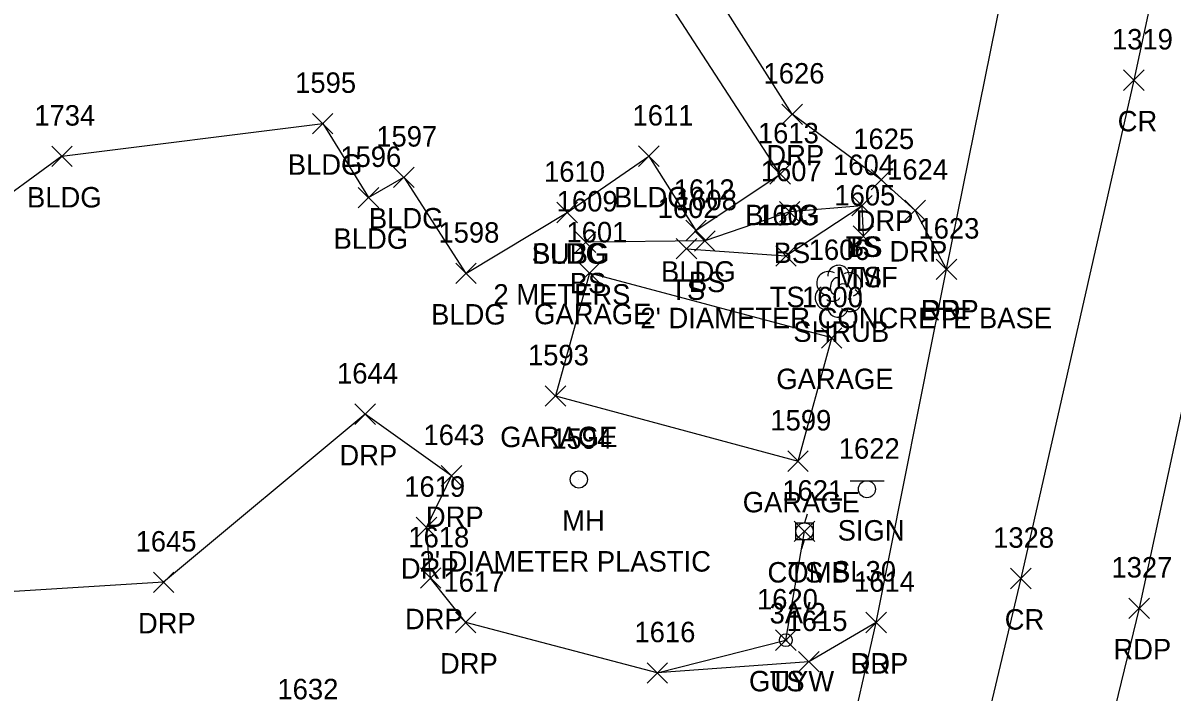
# Model space of a CAD drawing. Extents: x 1477930 to 1480780, y 774090 to 784647.
# Drawn here: x 1479284.7 to 1479397, y 774509.5 to 774574.9 of the extents above; entities that cross this region are included whole.
import ezdxf

# ---------------------------------------------------------------- set-up
doc = ezdxf.new("R2010")
doc.units = 0
for name, color, linetype in [('L_A', 7, 'Continuous'), ('L_C', 7, 'Continuous'), ('L_I', 7, 'Continuous'), ('L_TIC', 7, 'Continuous'), ('LBC', 7, 'Continuous'), ('LELB', 7, 'Continuous'), ('LSH', 7, 'Continuous'), ('P_A', 7, 'Continuous'), ('P_I', 7, 'Continuous'), ('P_TIC', 7, 'Continuous'), ('PET', 7, 'Continuous'), ('PRC', 7, 'Continuous'), ('R_A', 7, 'Continuous'), ('R_I', 7, 'Continuous'), ('R_TIC', 7, 'Continuous'), ('RDP', 7, 'Continuous'), ('S_A', 7, 'Continuous'), ('S_C', 7, 'Continuous'), ('S_I', 7, 'Continuous'), ('SSGN', 7, 'Continuous'), ('U_A', 7, 'Continuous'), ('U_C', 7, 'Continuous'), ('U_I', 7, 'Continuous'), ('U_TIC', 7, 'Continuous'), ('UP', 7, 'Continuous'), ('UPGW', 7, 'Continuous'), ('UUMH', 7, 'Continuous')]:
    doc.layers.add(name, color=color, linetype=linetype)

msp = doc.modelspace()

# ---------------------------------------------------------------- linework, layer by layer
at = {"layer": 'L_TIC'}
for points in [[(1479312.99, 774564.07), (1479314.99, 774566.07)], [(1479314.99, 774564.07), (1479312.99, 774566.07)], [(1479287.53, 774560.87), (1479289.53, 774562.87)], [(1479289.53, 774560.87), (1479287.53, 774562.87)], [(1479344.84, 774560.88), (1479346.84, 774562.88)], [(1479346.84, 774560.88), (1479344.84, 774562.88)], [(1479357.65, 774559.14), (1479359.65, 774561.14)], [(1479359.65, 774559.14), (1479357.65, 774561.14)], [(1479320.91, 774558.82), (1479322.91, 774560.82)], [(1479322.91, 774558.82), (1479320.91, 774560.82)], [(1479317.46, 774556.83), (1479319.46, 774558.83)], [(1479319.46, 774556.83), (1479317.46, 774558.83)], [(1479365.64, 774556.04), (1479367.64, 774558.04)], [(1479367.64, 774556.04), (1479365.64, 774558.04)], [(1479365.64, 774556.04), (1479367.64, 774558.04)], [(1479367.64, 774556.04), (1479365.64, 774558.04)], [(1479336.86, 774555.38), (1479338.86, 774557.38)], [(1479338.86, 774555.38), (1479336.86, 774557.38)], [(1479358.58, 774555.44), (1479360.58, 774557.44)], [(1479360.58, 774555.44), (1479358.58, 774557.44)], [(1479349.43, 774553.62), (1479351.43, 774555.62)], [(1479351.43, 774553.62), (1479349.43, 774555.62)], [(1479338.67, 774552.48), (1479340.67, 774554.48)], [(1479340.67, 774552.48), (1479338.67, 774554.48)], [(1479350.3, 774552.6), (1479352.3, 774554.6)], [(1479352.3, 774552.6), (1479350.3, 774554.6)], [(1479365.77, 774553.07), (1479367.77, 774555.07)], [(1479367.77, 774553.07), (1479365.77, 774555.07)], [(1479365.77, 774553.07), (1479367.77, 774555.07)], [(1479367.77, 774553.07), (1479365.77, 774555.07)], [(1479348.51, 774551.84), (1479350.51, 774553.84)], [(1479350.51, 774551.84), (1479348.51, 774553.84)], [(1479358.22, 774551.13), (1479360.22, 774553.13)], [(1479360.22, 774551.13), (1479358.22, 774553.13)], [(1479326.98, 774549.43), (1479328.98, 774551.43)], [(1479328.98, 774549.43), (1479326.98, 774551.43)], [(1479339.04, 774549.46), (1479341.04, 774551.46)], [(1479341.04, 774549.46), (1479339.04, 774551.46)], [(1479362.69, 774543.12), (1479364.69, 774545.12)], [(1479364.69, 774543.12), (1479362.69, 774545.12)], [(1479335.72, 774537.45), (1479337.72, 774539.45)], [(1479337.72, 774537.45), (1479335.72, 774539.45)], [(1479359.4, 774531.08), (1479361.4, 774533.08)], [(1479361.4, 774531.08), (1479359.4, 774533.08)], [(1479360.03, 774524.22), (1479362.03, 774526.22)], [(1479362.03, 774524.22), (1479360.03, 774526.22)], [(1479358.21, 774513.59), (1479360.21, 774515.59)], [(1479360.21, 774513.59), (1479358.21, 774515.59)], [(1479345.66, 774510.39), (1479347.66, 774512.39)], [(1479347.66, 774510.39), (1479345.66, 774512.39)]]:
    msp.add_lwpolyline(points, dxfattribs=at)
at = {"layer": 'LBC'}
for points in [[(1479288.53, 774561.87), (1479280.58, 774556.08), (1479280.86, 774553.15), (1479266.83, 774543.78), (1479264.18, 774547.87), (1479260.06, 774554.44), (1479272.44, 774562.55), (1479262.77, 774577.67), (1479295.55, 774599.42), (1479305.58, 774605.99), (1479303.57, 774609.45), (1479310.55, 774613.97), (1479312.86, 774610.52), (1479322.29, 774616.29), (1479331.34, 774602.22)], [(1479313.99, 774565.07), (1479318.46, 774557.83), (1479321.91, 774559.82), (1479327.98, 774550.43), (1479337.86, 774556.38), (1479345.84, 774561.88), (1479350.43, 774554.62), (1479358.65, 774560.14), (1479331.34, 774602.22)], [(1479288.53, 774561.87), (1479313.99, 774565.07)], [(1479336.72, 774538.45), (1479360.4, 774532.08), (1479363.69, 774544.12), (1479340.04, 774550.46)], [(1479340.04, 774550.46), (1479336.72, 774538.45)]]:
    msp.add_lwpolyline(points, dxfattribs=at)
at = {"layer": 'LELB'}
for points in [[(1479366.64, 774557.04), (1479359.58, 774556.44), (1479351.3, 774553.6), (1479339.67, 774553.48)], [(1479349.51, 774552.84), (1479359.22, 774552.13), (1479366.64, 774557.04), (1479366.77, 774554.07)], [(1479346.66, 774511.39), (1479359.21, 774514.59), (1479361.03, 774525.22)]]:
    msp.add_lwpolyline(points, dxfattribs=at)
at = {"layer": 'LSH'}
msp.add_line((1479364.31, 774548.74), (1479364.31, 774548.74), dxfattribs=at)
msp.add_line((1479364.31, 774548.74), (1479364.31, 774548.74), dxfattribs=at)
msp.add_arc((1479364.36, 774550.17), 1.05, 335.5272, 180.9563, dxfattribs=at)
for centre, major_axis, ratio, start_param, end_param in [((1479363.52, 774549.41), (1.21, -0.51), 0.895232, 1.570796, 4.712389), ((1479364.1, 774549.2), (-0.208, -0.792), 0.645439, 3.141593, 6.283185), ((1479365.35, 774549.32), (-1.14, -0.48), 0.949671, 1.570796, 4.712389), ((1479363.23, 774548.03), (0.58, -1.04), 0.959034, 3.141593, 6.283185), ((1479364.81, 774548.57), (-0.5, 0.667), 0.989748, 3.141593, 6.283185), ((1479365.31, 774547.91), (-1.09, 0.79), 0.841452, 1.570796, 4.712389), ((1479364.31, 774547.24), (0.26, 1.06), 0.942809, 1.570796, 4.712389), ((1479363.85, 774547.99), (-0.625, -0.083), 0.423636, 0, 3.141593)]:
    msp.add_ellipse(centre, major_axis=major_axis, ratio=ratio, start_param=start_param, end_param=end_param, dxfattribs=at)
at = {"layer": 'P_TIC'}
for points in [[(1479392.18, 774568.31), (1479394.18, 774570.31)], [(1479394.18, 774568.31), (1479392.18, 774570.31)], [(1479373.9, 774549.83), (1479375.9, 774551.83)], [(1479375.9, 774549.83), (1479373.9, 774551.83)], [(1479381.15, 774519.62), (1479383.15, 774521.62)], [(1479383.15, 774519.62), (1479381.15, 774521.62)], [(1479392.7, 774516.71), (1479394.7, 774518.71)], [(1479394.7, 774516.71), (1479392.7, 774518.71)], [(1479367.03, 774515.32), (1479369.03, 774517.32)], [(1479369.03, 774515.32), (1479367.03, 774517.32)]]:
    msp.add_lwpolyline(points, dxfattribs=at)
at = {"layer": 'PET'}
for points in [[(1479713.99, 774833.47), (1479663.95, 774806), (1479649, 774797.94), (1479602.12, 774772.9), (1479559.82, 774750.06), (1479518.06, 774728.17), (1479475.57, 774706.69), (1479465.7, 774701.25), (1479434.17, 774686.11), (1479428.66, 774666.26), (1479418.77, 774633.96), (1479413.82, 774614.69), (1479404.23, 774566.57), (1479393.7, 774517.71), (1479389.34, 774499.77)], [(1479290.45, 774211), (1479306.91, 774277.39), (1479311.78, 774295.77), (1479318.73, 774320.25), (1479320.95, 774328.78), (1479324.18, 774341.9), (1479331.38, 774365.72), (1479345.79, 774423.22), (1479362.09, 774490.12), (1479368.03, 774516.32), (1479374.9, 774550.83), (1479383.52, 774593.51), (1479391.98, 774640.39), (1479380.39, 774660.29), (1479367.57, 774658.29), (1479344.84, 774648.04), (1479309.03, 774631.85), (1479275.88, 774616.72), (1479247.66, 774604.4), (1479226.65, 774595.78), (1479182.4, 774576.78), (1479137.48, 774556.65)]]:
    msp.add_lwpolyline(points, dxfattribs=at)
at = {"layer": 'PRC'}
msp.add_lwpolyline([(1479418.32, 774694.97), (1479413.6, 774667.54), (1479403.41, 774616.88), (1479393.18, 774569.31), (1479382.15, 774520.62), (1479370.95, 774473.44), (1479362, 774437.8), (1479350.26, 774392.93), (1479347.88, 774382.5), (1479334.29, 774330.6), (1479333.84, 774328.63), (1479325.02, 774295.54), (1479313.51, 774250.57), (1479296.99, 774187.82), (1479284.93, 774140.68)], dxfattribs=at)
at = {"layer": 'R_TIC'}
for points in [[(1479358.82, 774564.98), (1479360.82, 774566.98)], [(1479360.82, 774564.98), (1479358.82, 774566.98)], [(1479367.53, 774558.58), (1479369.53, 774560.58)], [(1479369.53, 774558.58), (1479367.53, 774560.58)], [(1479370.84, 774555.59), (1479372.84, 774557.59)], [(1479372.84, 774555.59), (1479370.84, 774557.59)], [(1479373.9, 774549.83), (1479375.9, 774551.83)], [(1479375.9, 774549.83), (1479373.9, 774551.83)], [(1479317.13, 774535.67), (1479319.13, 774537.67)], [(1479319.13, 774535.67), (1479317.13, 774537.67)], [(1479325.57, 774529.65), (1479327.57, 774531.65)], [(1479327.57, 774529.65), (1479325.57, 774531.65)], [(1479323.13, 774524.6), (1479325.13, 774526.6)], [(1479325.13, 774524.6), (1479323.13, 774526.6)], [(1479323.53, 774519.66), (1479325.53, 774521.66)], [(1479325.53, 774519.66), (1479323.53, 774521.66)], [(1479297.46, 774519.25), (1479299.46, 774521.25)], [(1479299.46, 774519.25), (1479297.46, 774521.25)], [(1479326.95, 774515.32), (1479328.95, 774517.32)], [(1479328.95, 774515.32), (1479326.95, 774517.32)], [(1479367.03, 774515.32), (1479369.03, 774517.32)], [(1479369.03, 774515.32), (1479367.03, 774517.32)], [(1479360.45, 774511.48), (1479362.45, 774513.48)], [(1479362.45, 774511.48), (1479360.45, 774513.48)], [(1479345.66, 774510.39), (1479347.66, 774512.39)], [(1479347.66, 774510.39), (1479345.66, 774512.39)]]:
    msp.add_lwpolyline(points, dxfattribs=at)
at = {"layer": 'RDP'}
for points in [[(1479374.9, 774550.83), (1479371.84, 774556.59), (1479368.53, 774559.58), (1479359.82, 774565.98), (1479341.26, 774595.27), (1479341.69, 774602.81), (1479341.23, 774609.01)], [(1479368.03, 774516.32), (1479361.45, 774512.48), (1479346.66, 774511.39), (1479327.95, 774516.32), (1479324.53, 774520.66), (1479324.13, 774525.6), (1479326.57, 774530.65), (1479318.13, 774536.67), (1479298.46, 774520.25), (1479259.37, 774517.83), (1479242.33, 774516.7), (1479243.5, 774532.48), (1479249.65, 774538.58), (1479246.27, 774545.9), (1479253.38, 774552.86), (1479239.84, 774569.3), (1479196.16, 774549.72), (1479150.61, 774530.18)]]:
    msp.add_lwpolyline(points, dxfattribs=at)
at = {"layer": 'SSGN'}
for p, q in [((1479365.49, 774530.17), (1479368.82, 774530.17)), ((1479367.13, 774529.34), (1479367.13, 774529.34))]:
    msp.add_line(p, q, dxfattribs=at)
msp.add_circle((1479367.13, 774529.34), 0.833, dxfattribs=at)
at = {"layer": 'U_TIC'}
for points in [[(1479336.86, 774555.38), (1479338.86, 774557.38)], [(1479338.86, 774555.38), (1479336.86, 774557.38)]]:
    msp.add_lwpolyline(points, dxfattribs=at)
at = {"layer": 'UP'}
for p, q in [((1479361.28, 774526.89), (1479361.03, 774526.05)), ((1479360.2, 774524.39), (1479360.2, 774526.05)), ((1479360.2, 774526.05), (1479361.87, 774526.05)), ((1479361.03, 774525.22), (1479361.03, 774525.22)), ((1479361.87, 774526.05), (1479361.87, 774524.39)), ((1479361.87, 774524.39), (1479360.2, 774524.39)), ((1479360.78, 774523.55), (1479361.03, 774524.39))]:
    msp.add_line(p, q, dxfattribs=at)
msp.add_circle((1479361.03, 774525.22), 0.833, dxfattribs=at)
at = {"layer": 'UPGW'}
for radius in [0.625, 0.0833]:
    msp.add_circle((1479359.21, 774514.59), radius, dxfattribs=at)
at = {"layer": 'UUMH'}
for p, q in [((1479339, 774530.29), (1479339, 774530.29)), ((1479339.84, 774530.29), (1479339.84, 774530.29))]:
    msp.add_line(p, q, dxfattribs=at)
msp.add_circle((1479339, 774530.29), 0.833, dxfattribs=at)

# ---------------------------------------------------------------- texts
at = {"layer": 'L_A'}
for s, p in [('BLDG', (1479310.58, 774560.07)), ('BLDG', (1479285.12, 774556.87)), ('BLDG', (1479342.43, 774556.88)), ('BLDG', (1479318.5, 774554.82)), ('BLDG', (1479355.24, 774555.14)), ('BLDG', (1479315.05, 774552.83)), ('BLDG', (1479334.45, 774551.38)), ('BS', (1479358.02, 774551.44)), ('TS', (1479365.05, 774552.04)), ('BS', (1479365.08, 774552.04)), ('BLDG', (1479347.02, 774549.62)), ('MMF', (1479364.06, 774549.07)), ('TS', (1479365.18, 774549.07)), ('BS', (1479338.11, 774548.48)), ('TS', (1479347.92, 774547.84)), ('BS', (1479349.74, 774548.6)), ('TS', (1479357.63, 774547.13)), ('BLDG', (1479324.57, 774545.43)), ('GARAGE', (1479334.64, 774545.46)), ('SHRUB', (1479359.94, 774543.74)), ('GARAGE', (1479358.28, 774539.12)), ('GARAGE', (1479331.32, 774533.45)), ('GARAGE', (1479355, 774527.08)), ('TS', (1479359.44, 774520.22)), ('TS', (1479357.62, 774509.59))]:
    msp.add_text(s, height=2, dxfattribs=at).set_placement(p)
at = {"layer": 'L_C'}
for s, p in [("2' DIAMETER CONCRETE BASE", (1479345.01, 774545.07)), ('3A/2', (1479357.62, 774516.22))]:
    msp.add_text(s, height=2, dxfattribs=at).set_placement(p)
at = {"layer": 'L_I'}
for s, p in [('1595', (1479311.3, 774568.07)), ('1734', (1479285.83, 774564.87)), ('1611', (1479344.24, 774564.88)), ('1597', (1479319.22, 774562.82)), ('1613', (1479356.48, 774563.14)), ('1596', (1479315.71, 774560.83)), ('1604', (1479363.82, 774560.04)), ('1604', (1479363.82, 774560.04)), ('1610', (1479335.6, 774559.38)), ('1607', (1479356.76, 774559.44)), ('1612', (1479348.26, 774557.62)), ('1605', (1479363.95, 774557.07)), ('1605', (1479363.95, 774557.07)), ('1609', (1479336.84, 774556.48)), ('1602', (1479346.7, 774555.84)), ('1608', (1479348.48, 774556.6)), ('1603', (1479356.4, 774555.13)), ('1598', (1479325.29, 774553.43)), ('1601', (1479337.79, 774553.46)), ('1606', (1479361.44, 774551.74)), ('1600', (1479360.78, 774547.12)), ('1593', (1479334.03, 774541.45)), ('1599', (1479357.7, 774535.08)), ('1621', (1479358.86, 774528.22)), ('1620', (1479356.39, 774517.59)), ('1616', (1479344.43, 774514.39))]:
    msp.add_text(s, height=2, dxfattribs=at).set_placement(p)
at = {"layer": 'P_A'}
for s, p in [('CR', (1479391.61, 774564.31)), ('RDP', (1479372.39, 774545.83)), ('CR', (1479380.58, 774515.62)), ('RDP', (1479391.19, 774512.71)), ('RDP', (1479365.52, 774511.32))]:
    msp.add_text(s, height=2, dxfattribs=at).set_placement(p)
at = {"layer": 'P_I'}
for s, p in [('1319', (1479391.05, 774572.31)), ('1623', (1479372.16, 774553.83)), ('1328', (1479379.45, 774523.62)), ('1327', (1479391, 774520.71)), ('1614', (1479365.86, 774519.32))]:
    msp.add_text(s, height=2, dxfattribs=at).set_placement(p)
at = {"layer": 'R_A'}
for p in [(1479357.31, 774560.98), (1479366.02, 774554.58), (1479369.33, 774551.59), (1479372.39, 774545.83), (1479315.62, 774531.67), (1479324.06, 774525.65), (1479321.62, 774520.6), (1479295.95, 774515.25), (1479322.02, 774515.66), (1479325.44, 774511.32), (1479365.52, 774511.32)]:
    msp.add_text('DRP', height=2, dxfattribs=at).set_placement(p)
at = {"layer": 'R_I'}
for s, p in [('1626', (1479357.03, 774568.98)), ('1625', (1479365.79, 774562.58)), ('1624', (1479369.1, 774559.59)), ('1623', (1479372.16, 774553.83)), ('1644', (1479315.39, 774539.67)), ('1643', (1479323.83, 774533.65)), ('1619', (1479321.95, 774528.6)), ('1645', (1479295.72, 774523.25)), ('1618', (1479322.35, 774523.66)), ('1617', (1479325.78, 774519.32)), ('1614', (1479365.86, 774519.32)), ('1615', (1479359.28, 774515.48)), ('1616', (1479344.43, 774514.39)), ('1632', (1479309.57, 774508.81))]:
    msp.add_text(s, height=2, dxfattribs=at).set_placement(p)
at = {"layer": 'S_A'}
msp.add_text('SIGN', height=2, dxfattribs=at).set_placement((1479364.27, 774524.32))
at = {"layer": 'S_C'}
msp.add_text('SL30', height=2, dxfattribs=at).set_placement((1479363.72, 774520.32))
at = {"layer": 'S_I'}
msp.add_text('1622', height=2, dxfattribs=at).set_placement((1479364.38, 774532.32))
at = {"layer": 'U_A'}
for s, p in [('SUBG', (1479334.39, 774551.38)), ('MH', (1479337.37, 774525.29)), ('COMB', (1479357.42, 774520.22)), ('GUYW', (1479355.61, 774509.59))]:
    msp.add_text(s, height=2, dxfattribs=at).set_placement(p)
at = {"layer": 'U_C'}
for s, p in [('2 METERS', (1479330.66, 774547.38)), ("2' DIAMETER PLASTIC", (1479323.45, 774521.29))]:
    msp.add_text(s, height=2, dxfattribs=at).set_placement(p)
at = {"layer": 'U_I'}
for s, p in [('1610', (1479335.6, 774559.38)), ('1594', (1479336.31, 774533.29)), ('1621', (1479358.86, 774528.22)), ('1620', (1479356.39, 774517.59))]:
    msp.add_text(s, height=2, dxfattribs=at).set_placement(p)

doc.saveas('drawing.dxf')
